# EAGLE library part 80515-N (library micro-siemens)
MICROPROCESSOR/PERIPHERAL DEVICE
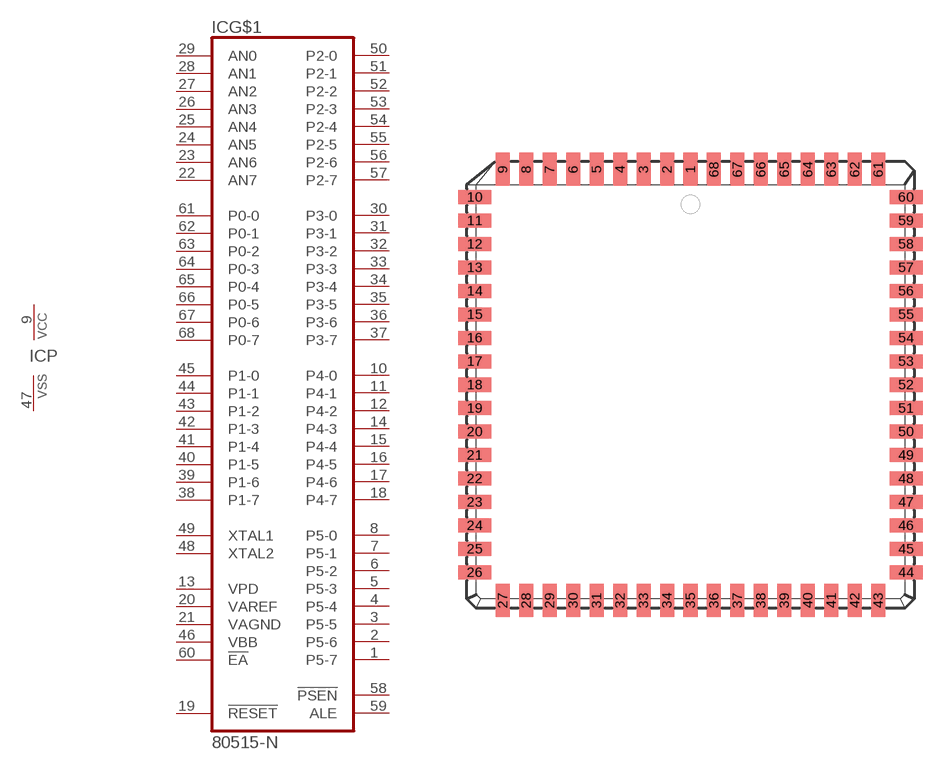
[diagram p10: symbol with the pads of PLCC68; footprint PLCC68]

Designator prefix IC; gates G$1=80515-N P=VCCVSS

## 80515-N (OC_FARNELL: unknown; OC_NEWARK: unknown)  [PLCC68]
1  G$1:P5-7
2  G$1:P5-6
3  G$1:P5-5
4  G$1:P5-4
5  G$1:P5-3
6  G$1:P5-2
7  G$1:P5-1
8  G$1:P5-0
9  P:VCC  pwr
10  G$1:P4-0
11  G$1:P4-1
12  G$1:P4-2
13  G$1:VPD  in
14  G$1:P4-3
15  G$1:P4-4
16  G$1:P4-5
17  G$1:P4-6
18  G$1:P4-7
19  G$1:!RESET  in
20  G$1:VAREF  in
21  G$1:VAGND  in
22  G$1:AN7  in
23  G$1:AN6  in
24  G$1:AN5  in
25  G$1:AN4  in
26  G$1:AN3  in
27  G$1:AN2  in
28  G$1:AN1  in
29  G$1:AN0  in
30  G$1:P3-0
31  G$1:P3-1
32  G$1:P3-2
33  G$1:P3-3
34  G$1:P3-4
35  G$1:P3-5
36  G$1:P3-6
37  G$1:P3-7
38  G$1:P1-7
39  G$1:P1-6
40  G$1:P1-5
41  G$1:P1-4
42  G$1:P1-3
43  G$1:P1-2
44  G$1:P1-1
45  G$1:P1-0
46  G$1:VBB  pas
47  P:VSS  pwr
48  G$1:XTAL2  pas
49  G$1:XTAL1  pas
50  G$1:P2-0
51  G$1:P2-1
52  G$1:P2-2
53  G$1:P2-3
54  G$1:P2-4
55  G$1:P2-5
56  G$1:P2-6
57  G$1:P2-7
58  G$1:!PSEN  out
59  G$1:ALE  out
60  G$1:!EA  in
61  G$1:P0-0
62  G$1:P0-1
63  G$1:P0-2
64  G$1:P0-3
65  G$1:P0-4
66  G$1:P0-5
67  G$1:P0-6
68  G$1:P0-7

## Footprint PLCC68 (pad centres in mm)
PLASTIC LEADED CHIP CARRIER square
smd 0.76 x 1.8: 1 0,11.67; 2 -1.27,11.67; 3 -2.54,11.67; 4 -3.81,11.67; 5 -5.08,11.67; 6 -6.35,11.67; 7 -7.62,11.67; 8 -8.89,11.67; 9 -10.16,11.67; 27 -10.16,-11.67; 28 -8.89,-11.67; 29 -7.62,-11.67; 30 -6.35,-11.67; 31 -5.08,-11.67; 32 -3.81,-11.67; 33 -2.54,-11.67; 34 -1.27,-11.67; 35 0,-11.67; 36 1.27,-11.67; 37 2.54,-11.67; 38 3.81,-11.67; 39 5.08,-11.67; 40 6.35,-11.67; 41 7.62,-11.67; 42 8.89,-11.67; 43 10.16,-11.67; 61 10.16,11.67; 62 8.89,11.67; 63 7.62,11.67; 64 6.35,11.67; 65 5.08,11.67; 66 3.81,11.67; 67 2.54,11.67; 68 1.27,11.67
smd 1.8 x 0.76: 10 -11.67,10.16; 11 -11.67,8.89; 12 -11.67,7.62; 13 -11.67,6.35; 14 -11.67,5.08; 15 -11.67,3.81; 16 -11.67,2.54; 17 -11.67,1.27; 18 -11.67,0; 19 -11.67,-1.27; 20 -11.67,-2.54; 21 -11.67,-3.81; 22 -11.67,-5.08; 23 -11.67,-6.35; 24 -11.67,-7.62; 25 -11.67,-8.89; 26 -11.67,-10.16; 44 11.67,-10.16; 45 11.67,-8.89; 46 11.67,-7.62; 47 11.67,-6.35; 48 11.67,-5.08; 49 11.67,-3.81; 50 11.67,-2.54; 51 11.67,-1.27; 52 11.67,0; 53 11.67,1.27; 54 11.67,2.54; 55 11.67,3.81; 56 11.67,5.08; 57 11.67,6.35; 58 11.67,7.62; 59 11.67,8.89; 60 11.67,10.16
